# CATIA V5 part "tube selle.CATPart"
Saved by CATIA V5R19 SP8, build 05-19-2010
Part number: tube selle
Bounding box of the stored display mesh (mm): x 0 to 200, y -7 to 7, z -6.974 to 6.974
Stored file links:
  G:\EU_thinkMotion\CFAO_2010\SIL_groupe1\SIL_groupe1\A reprendre\scador\monocycle\tube selle.CATPart
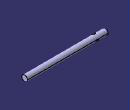
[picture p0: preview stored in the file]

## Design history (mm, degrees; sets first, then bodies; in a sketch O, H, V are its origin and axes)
Body1 (main body)
  Sketch1 on yz-plane, origin (0, 0, 0), H (0, 1, 0), V (0, 0, 1)
    circle A1 centre (0, 0) radius 7
    radius A1 = 7
  Pad1: profile Sketch1, direction (1, 0, 0), length 200
  Sketch2 on {plane type Tangent, Support face of Pad1 from Sketch1.A1, RefPoint {point type OnSurface, Support face of Pad1 from Sketch1.A1, RefPoint {point stored without definition}, Length 0, Direction (0, 923.8795, 382.6834)}}, origin (24.1006, -2.6788, 6.4672), H (1, 0, 0), V (0, -0.9239, -0.3827)
    point P1 (0.8994, 2.1005)
    reference intersected line E1 through (-24.1006, 0) direction (0, 1) from yz-plane
    reference intersected line E2 through (0, -2.8995) direction (1, 0) from zx-plane
    distance P1 E1 = 25
    distance P1 E2 = 5
  Hole1: placed by Sketch2, at (25, -4.4245, 5.4244) direction (0, 0.6321, -0.7749), diameter 8, through (limit type 6)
